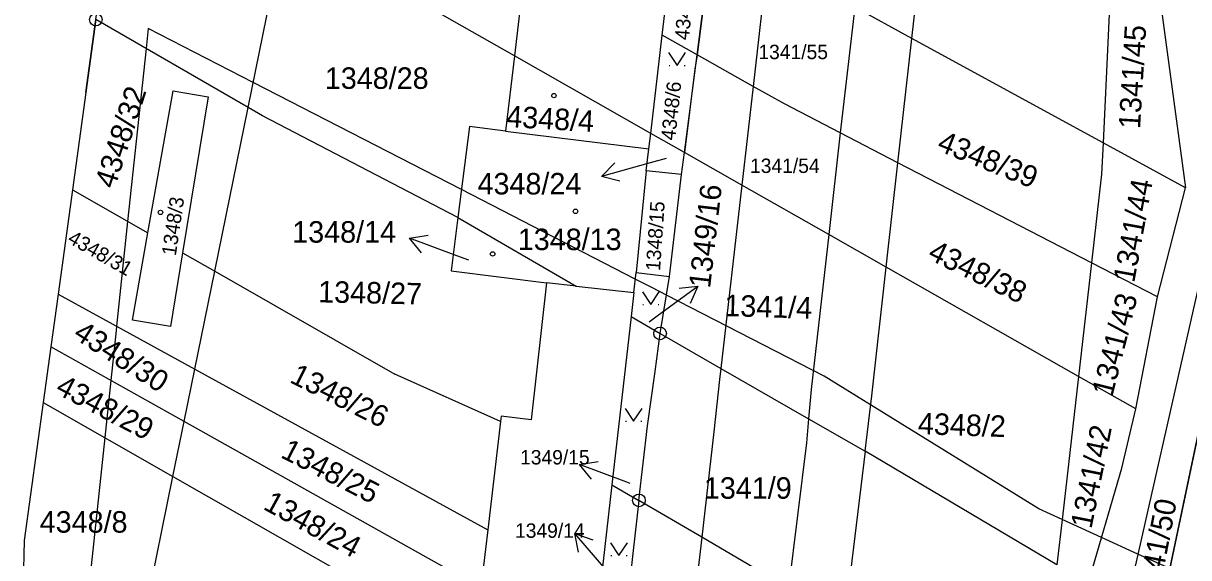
# Model space of a CAD drawing. Extents: x -735036 to -734743, y -1144813 to -1144181.
# Drawn here: x -734893.4 to -734801.1, y -1144606.3 to -1144564.1 of the extents above; entities that cross this region are included whole.
import ezdxf

# ---------------------------------------------------------------- set-up
doc = ezdxf.new("R2010")
doc.units = 0
for name, color, linetype in [('A3_SIT_OBJEKTY_N01', 7, 'Continuous'), ('BPEJ', 7, 'Continuous'), ('Katastr_HRANICE DRÁHY', 7, 'Continuous'), ('Katastr_Hranice parcel', 7, 'Continuous'), ('Katastr_Parcelní čísla', 7, 'Continuous'), ('Katastr_Slučkované čáry', 7, 'Continuous'), ('Katastr_Značky kultur', 7, 'Continuous')]:
    doc.layers.add(name, color=color, linetype=linetype)

msp = doc.modelspace()

# ---------------------------------------------------------------- linework, layer by layer
at = {"layer": 'A3_SIT_OBJEKTY_N01'}
for points in [[(-734888.44, -1144569.554), (-734887.65, -1144563.8), (-734885.58, -1144548.75), (-734874.6, -1144550.79), (-734868.084, -1144506.936)], [(-734833.069, -1144512.138), (-734834.23, -1144521.36), (-734836.63, -1144539.96), (-734838.79, -1144556.7), (-734840.06, -1144566.59), (-734840.228, -1144567.714), (-734841.06, -1144574.32)]]:
    msp.add_lwpolyline(points, dxfattribs=at)
at = {"layer": 'BPEJ'}
msp.add_lwpolyline([(-734799.83, -1144593.94), (-734802.63, -1144607.21), (-734805.16, -1144606.06), (-734808.05, -1144604.75), (-734811.16, -1144603.33), (-734813, -1144602.5), (-734826.32, -1144594.27), (-734830, -1144592), (-734842.48, -1144585.59), (-734843.64, -1144584.99), (-734844.95, -1144584.32), (-734858.71, -1144577.24), (-734875.19, -1144568.77), (-734883.5, -1144564.5), (-734883.67, -1144566.1), (-734885.13, -1144579.76), (-734886.01, -1144588.05), (-734886.05, -1144588.39), (-734886.47, -1144592.33), (-734886.95, -1144596.85), (-734888.29, -1144609.47)], dxfattribs=at)
at = {"layer": 'Katastr_HRANICE DRÁHY'}
for points in [[(-734823.06, -1144565.29), (-734821.17, -1144548.5)], [(-734840.06, -1144566.59), (-734838.79, -1144556.7)], [(-734803.9, -1144558.55), (-734801.41, -1144577.1)], [(-734887.65, -1144563.8), (-734889.5, -1144577.27)], [(-734807.92, -1144573.55), (-734823.06, -1144565.29)], [(-734841.06, -1144574.32), (-734840.06, -1144566.59)], [(-734801.41, -1144577.1), (-734807.92, -1144573.55)], [(-734841.28, -1144576.06), (-734841.06, -1144574.32)], [(-734842.23, -1144584.11), (-734841.28, -1144576.06)], [(-734889.5, -1144577.27), (-734890.64, -1144585.51)], [(-734858.99, -1144579.44), (-734859.52, -1144583.67)], [(-734858.99, -1144579.44), (-734849.62, -1144584.88)], [(-734859.52, -1144583.67), (-734851.98, -1144584.62)], [(-734842.99, -1144588.62), (-734842.23, -1144584.11)], [(-734849.62, -1144584.88), (-734851.98, -1144584.62)], [(-734890.64, -1144585.51), (-734891.21, -1144589.67)], [(-734843.38, -1144591.64), (-734842.99, -1144588.62)], [(-734891.21, -1144589.67), (-734891.82, -1144594.07)], [(-734843.99, -1144595.92), (-734843.38, -1144591.64)], [(-734891.82, -1144594.07), (-734893.32, -1144605)], [(-734844.66, -1144601.82), (-734843.99, -1144595.92)], [(-734844.66, -1144601.82), (-734845.64, -1144610.44)], [(-734893.32, -1144605), (-734893.39, -1144608.37)]]:
    msp.add_lwpolyline(points, dxfattribs=at)
at = {"layer": 'Katastr_Hranice parcel'}
for points in [[(-734842.81, -1144565.04), (-734841.63, -1144555.15)], [(-734875.6, -1144570.76), (-734872.67, -1144556.37)], [(-734854.52, -1144566.67), (-734872.67, -1144556.37)], [(-734807.12, -1144556.54), (-734807.92, -1144573.55)], [(-734853.62, -1144558.97), (-734854.52, -1144566.67)], [(-734823.06, -1144565.29), (-734827.58, -1144562.82)], [(-734875.6, -1144570.76), (-734887.65, -1144563.8)], [(-734843.73, -1144572.8), (-734842.81, -1144565.04)], [(-734840.06, -1144566.59), (-734842.81, -1144565.04)], [(-734824.16, -1144575.12), (-734823.06, -1144565.29)], [(-734854.52, -1144566.67), (-734855.22, -1144572.62)], [(-734843.73, -1144572.8), (-734854.52, -1144566.67)], [(-734835.63, -1144569.08), (-734840.06, -1144566.59)], [(-734883.54, -1144580.67), (-734881.54, -1144569.44)], [(-734881.54, -1144569.44), (-734878.76, -1144569.92)], [(-734833.15, -1144570.47), (-734835.63, -1144569.08)], [(-734878.76, -1144569.92), (-734880.78, -1144582.24)], [(-734878.24, -1144583.69), (-734875.6, -1144570.76)], [(-734874.46, -1144571.42), (-734875.6, -1144570.76)], [(-734828.72, -1144572.76), (-734833.15, -1144570.47)], [(-734858.99, -1144579.44), (-734874.46, -1144571.42)], [(-734858.08, -1144572.26), (-734858.99, -1144579.44)], [(-734855.22, -1144572.62), (-734858.08, -1144572.26)], [(-734855.22, -1144572.62), (-734843.88, -1144574.02)], [(-734843.88, -1144574.02), (-734843.73, -1144572.8)], [(-734841.06, -1144574.32), (-734843.73, -1144572.8)], [(-734824.16, -1144575.12), (-734828.72, -1144572.76)], [(-734844.09, -1144575.76), (-734843.88, -1144574.02)], [(-734807.92, -1144573.55), (-734808.04, -1144576.02)], [(-734836.52, -1144576.89), (-734841.06, -1144574.32)], [(-734844.09, -1144575.76), (-734844.89, -1144583.8)], [(-734841.28, -1144576.06), (-734844.09, -1144575.76)], [(-734825.09, -1144583.38), (-734824.16, -1144575.12)], [(-734808.84, -1144583.03), (-734824.16, -1144575.12)], [(-734808.04, -1144576.02), (-734808.84, -1144583.03)], [(-734889.5, -1144577.27), (-734883.54, -1144580.67)], [(-734829.64, -1144580.8), (-734836.52, -1144576.89)], [(-734798.65, -1144577.31), (-734805.94, -1144609.48)], [(-734803.62, -1144585.73), (-734801.41, -1144577.1)], [(-734884.76, -1144587.57), (-734883.54, -1144580.67)], [(-734825.09, -1144583.38), (-734829.64, -1144580.8)], [(-734880.78, -1144582.24), (-734881.74, -1144588.08)], [(-734880.78, -1144582.24), (-734878.24, -1144583.69)], [(-734808.84, -1144583.03), (-734809.87, -1144592.02)], [(-734803.62, -1144585.73), (-734808.84, -1144583.03)], [(-734879.82, -1144591.44), (-734878.24, -1144583.69)], [(-734878.24, -1144583.69), (-734863.97, -1144591.84)], [(-734845.07, -1144585.39), (-734844.89, -1144583.8)], [(-734844.89, -1144583.8), (-734842.23, -1144584.11)], [(-734826.23, -1144593.55), (-734825.09, -1144583.38)], [(-734809.87, -1144592.02), (-734825.09, -1144583.38)], [(-734851.98, -1144584.62), (-734853.19, -1144595.45)], [(-734849.62, -1144584.88), (-734845.07, -1144585.39)], [(-734890.64, -1144585.51), (-734879.82, -1144591.44)], [(-734845.07, -1144585.39), (-734845.28, -1144587.28)], [(-734805.34, -1144594.59), (-734803.62, -1144585.73)], [(-734881.74, -1144588.08), (-734884.76, -1144587.57)], [(-734845.28, -1144587.28), (-734846.8, -1144600.6)], [(-734845.28, -1144587.28), (-734842.99, -1144588.62)], [(-734842.99, -1144588.62), (-734838.18, -1144591.38)], [(-734880.66, -1144595.58), (-734891.21, -1144589.67)], [(-734880.66, -1144595.58), (-734879.82, -1144591.44)], [(-734879.82, -1144591.44), (-734856.63, -1144604.15)], [(-734838.18, -1144591.38), (-734831.24, -1144595.37)], [(-734855.61, -1144595.57), (-734863.97, -1144591.84)], [(-734809.87, -1144592.02), (-734811.14, -1144603.11)], [(-734805.34, -1144594.59), (-734809.87, -1144592.02)], [(-734891.82, -1144594.07), (-734881.55, -1144599.93)], [(-734826.76, -1144597.94), (-734826.23, -1144593.55)], [(-734814.3, -1144662.64), (-734799.83, -1144593.94)], [(-734855.56, -1144595.17), (-734855.61, -1144595.57)], [(-734853.19, -1144595.45), (-734855.56, -1144595.17)], [(-734806.45, -1144599.27), (-734805.34, -1144594.59)], [(-734881.55, -1144599.93), (-734880.66, -1144595.58)], [(-734857.17, -1144608.74), (-734880.66, -1144595.58)], [(-734855.61, -1144595.57), (-734856.63, -1144604.15)], [(-734831.24, -1144595.37), (-734826.76, -1144597.94)], [(-734826.76, -1144597.94), (-734828.38, -1144611.37)], [(-734811.57, -1144606.92), (-734826.76, -1144597.94)], [(-734883.7, -1144610.47), (-734881.55, -1144599.93)], [(-734881.55, -1144599.93), (-734858.79, -1144612.91)], [(-734809.1, -1144608.38), (-734806.45, -1144599.27)], [(-734846.8, -1144600.6), (-734847.79, -1144609.19)], [(-734846.8, -1144600.6), (-734844.66, -1144601.82)], [(-734839.69, -1144604.74), (-734844.66, -1144601.82)], [(-734811.14, -1144603.11), (-734811.57, -1144606.92)], [(-734856.63, -1144604.15), (-734857.17, -1144608.74)], [(-734832.82, -1144608.77), (-734839.69, -1144604.74)]]:
    msp.add_lwpolyline(points, dxfattribs=at)
at = {"layer": 'Katastr_Parcelní čísla'}
for p, q in [((-734842.5, -1144574.79), (-734843.76, -1144575.14)), ((-734846.165, -1144576.578), (-734847.617, -1144576.2)), ((-734861.873, -1144582.25), (-734862.833, -1144581.096)), ((-734858.12, -1144582.83), (-734859.08, -1144582.48)), ((-734841.483, -1144585.031), (-734839.991, -1144584.869)), ((-734843.85, -1144587.69), (-734843.22, -1144587.23)), ((-734848.422, -1144600.148), (-734849.377, -1144598.991)), ((-734845.36, -1144600.49), (-734845.63, -1144600.39)), ((-734849.452, -1144605.917), (-734849.734, -1144604.442))]:
    msp.add_line(p, q, dxfattribs=at)
for points in [[(-734843.76, -1144575.14), (-734847.617, -1144576.2), (-734846.562, -1144575.132)], [(-734859.08, -1144582.48), (-734862.833, -1144581.096), (-734861.354, -1144580.842)], [(-734843.22, -1144587.23), (-734839.991, -1144584.869), (-734840.598, -1144586.242)], [(-734845.63, -1144600.39), (-734849.377, -1144598.991), (-734847.897, -1144598.743)], [(-734847.12, -1144607.47), (-734849.734, -1144604.442), (-734848.317, -1144604.936)]]:
    msp.add_lwpolyline(points, dxfattribs=at)
at = {"layer": 'Katastr_Slučkované čáry'}
for points in [[(-734834.48, -1144559.05), (-734835.63, -1144569.08)], [(-734827.58, -1144562.82), (-734828.72, -1144572.76)], [(-734835.63, -1144569.08), (-734836.52, -1144576.89)], [(-734828.72, -1144572.76), (-734829.64, -1144580.8)], [(-734836.52, -1144576.89), (-734838.18, -1144591.38)], [(-734829.64, -1144580.8), (-734831.04, -1144593.06)], [(-734838.18, -1144591.38), (-734838.28, -1144592.26)], [(-734838.28, -1144592.26), (-734838.72, -1144596.41)], [(-734831.04, -1144593.06), (-734831.24, -1144595.37)], [(-734831.24, -1144595.37), (-734831.41, -1144597.28)], [(-734838.72, -1144596.41), (-734839.69, -1144604.74)], [(-734831.41, -1144597.28), (-734832.82, -1144608.77)], [(-734839.69, -1144604.74), (-734840.68, -1144613.32)]]:
    msp.add_lwpolyline(points, dxfattribs=at)
at = {"layer": 'Katastr_Značky kultur'}
for p, q in [((-734842.31, -1144566.415), (-734841.64, -1144567.42)), ((-734841.64, -1144567.42), (-734840.97, -1144566.415)), ((-734842.277, -1144567.42), (-734842.21, -1144567.42)), ((-734841.071, -1144567.42), (-734841.003, -1144567.42)), ((-734844.39, -1144585.325), (-734843.72, -1144586.33)), ((-734843.72, -1144586.33), (-734843.05, -1144585.325)), ((-734844.356, -1144586.33), (-734844.29, -1144586.33)), ((-734843.15, -1144586.33), (-734843.084, -1144586.33)), ((-734843.04, -1144588.62), (-734842.94, -1144588.62)), ((-734845.75, -1144594.545), (-734845.08, -1144595.55)), ((-734845.08, -1144595.55), (-734844.41, -1144594.545)), ((-734845.716, -1144595.55), (-734845.65, -1144595.55)), ((-734844.51, -1144595.55), (-734844.443, -1144595.55)), ((-734844.71, -1144601.82), (-734844.61, -1144601.82)), ((-734846.91, -1144605.185), (-734846.24, -1144606.19)), ((-734846.24, -1144606.19), (-734845.57, -1144605.185)), ((-734846.877, -1144606.19), (-734846.81, -1144606.19)), ((-734845.671, -1144606.19), (-734845.603, -1144606.19))]:
    msp.add_line(p, q, dxfattribs=at)
for centre, radius in [((-734887.65, -1144563.8), 0.499), ((-734851.39, -1144569.81), 0.175), ((-734882.53, -1144579.05), 0.175), ((-734849.68, -1144578.96), 0.175), ((-734856.24, -1144582.33), 0.175), ((-734842.99, -1144588.62), 0.499), ((-734844.66, -1144601.82), 0.499)]:
    msp.add_circle(centre, radius, dxfattribs=at)

# ---------------------------------------------------------------- texts
at = {"layer": 'Katastr_Parcelní čísla'}
for s, height, rotation, p in [('4348/20', 1.14, 85.455, (-734840.688, -1144565.457)), ('1341/45', 1.7, 86.52627, (-734804.997, -1144572.483)), ('4348/32', 1.7, 71.92764, (-734886.167, -1144577.248)), ('4348/6', 1.14, 83.8845, (-734841.793, -1144573.389)), ('4348/4', 1.7, 356.64444, (-734855.201, -1144572.285)), ('4348/39', 1.7, 338.08932, (-734821.153, -1144574.111)), ('1341/44', 1.7, 79.64415, (-734805.458, -1144584.662)), ('1349/16', 1.7, 83.39346, (-734839.03, -1144585.09)), ('1348/3', 1.14, 81.64926, (-734881.32, -1144582.524)), ('1348/15', 1.14, 86.06448, (-734842.99, -1144583.708)), ('4348/31', 1.14, 330.23547, (-734889.96, -1144581.39)), ('4348/38', 1.7, 333.99027, (-734821.895, -1144582.69)), ('1348/27', 1.7, 358.76061, (-734870.063, -1144586.158)), ('1341/4', 1.7, 358.29018, (-734837.921, -1144587.244)), ('1341/43', 1.7, 75.79134, (-734807.192, -1144593.672)), ('4348/30', 1.7, 327.42684, (-734889.533, -1144588.935)), ('1348/26', 1.7, 333.43497, (-734872.385, -1144592.448)), ('4348/29', 1.7, 332.34471, (-734890.941, -1144593.302)), ('4348/2', 1.7, 358.03449, (-734822.6, -1144596.578)), ('1341/42', 1.7, 78.58224, (-734808.845, -1144604.121)), ('1348/25', 1.7, 332.82063, (-734873.104, -1144598.377)), ('1348/24', 1.7, 331.31088, (-734874.487, -1144602.47)), ('1341/50', 1.7, 79.13709, (-734803.622, -1144609.95))]:
    msp.add_text(s, height=height, rotation=rotation, dxfattribs=at).set_placement(p)
for s, height, p in [('1341/55', 1.14, (-734835.206, -1144566.93)), ('1348/28', 1.7, (-734869.524, -1144569.28)), ('1341/54', 1.14, (-734835.869, -1144575.93)), ('4348/24', 1.7, (-734857.436, -1144577.63)), ('1348/14', 1.7, (-734872.104, -1144581.44)), ('1348/13', 1.7, (-734854.251, -1144582.03)), ('1349/15', 1.14, (-734854.071, -1144598.98)), ('1341/9', 1.7, (-734839.521, -1144601.69)), ('4348/8', 1.7, (-734892.093, -1144604.37)), ('1349/14', 1.14, (-734854.469, -1144604.78))]:
    msp.add_text(s, height=height, dxfattribs=at).set_placement(p)

doc.saveas('drawing.dxf')
